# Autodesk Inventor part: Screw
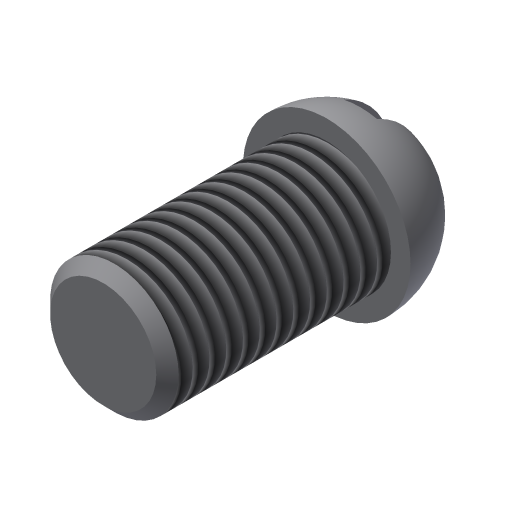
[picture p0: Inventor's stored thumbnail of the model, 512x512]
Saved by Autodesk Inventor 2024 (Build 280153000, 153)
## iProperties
Shininess: 77.0
Length Units: 11269
Angle Units: 11279
Time Units: 11290
Mass Units: 11283
Length Display Precision: 3
Angle Display Precision: 2
Created: 2002-01
Part Number: Screw
Document SubType Name: Modeling
Designer: ***
Density: 1 g/cm^3
Material: Generic
Appearance: Default
Density: 0.0
Volumn: 0.0
Area: 0.0
PropertySet Name: Model Information
Control State: 0
Master: False
Checked Out: False
Author: ***
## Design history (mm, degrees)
sketch "Sketch1"
  geometry: L1 (-0.061, 13.328)-(-0.061, -1.672); L2 (-0.061, -1.672)-(14.939, -1.672); A1 r 15 centre (-0.061, -1.672) between (14.939, -1.672) and (-0.061, 13.328)
  constraints: 4 end point, 2 point on circle, 1 centre point
  dimensions: "d0" = 15 radius of A1
revolve "Revolution1" sketch "Sketch1" stored, may be unused: angle "d3" = 90 deg
workplane "Work Plane2"
sketch "Sketch3"
  geometry: L1 (-3, 26)-(3, 26); L2 (3, 26)-(3, 6); L3 (3, 6)-(-3, 6); L4 (-3, 6)-(-3, 26); L5 (-15, 0)-(15, 0) reference
  constraints: 8 end point, 2 parallel, 1 horizontal, 1 perpendicular
  dimensions: "d11" = 6 distance of L1.start L1.end; "d12" = 20 distance of L3.end L1.start; "d13" = 6 distance between parallel lines of L5 L3; "d14" = 12 distance from line of L4 L5.start
extrude "Extrusion2" cut sketch "Sketch3" extent not by distance; stored distance "d15" = 10; taper "d16" = 0 deg
sketch "Sketch4"
  geometry: C1 r 11.5 at (0, 0); C2 r 15 at (0, 0) reference
  constraints: 1 centre point, 1 concentric
  dimensions: "d17" = 23 diameter of C1
extrude "Extrusion3" join sketch "Sketch4" distance "d18" = 40; taper "d19" = 0 deg
chamfer "Chamfer1" distance "d20" = 2; stored, may be unused: second distance "d21" = 2, angle "d24" = 45 deg
thread "Thread1" dims "d22" = 10, "d23" = 0
body "Solid1"
